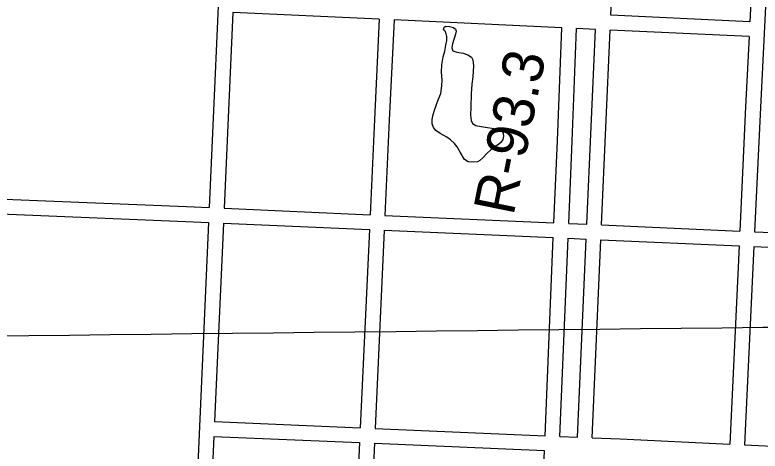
# Model space of a CAD drawing. Extents: x 3677843 to 3715951, y 511991 to 537744.
# Drawn here: x 3689113 to 3690620, y 529372 to 530256 of the extents above; entities that cross this region are included whole.
import ezdxf

# ---------------------------------------------------------------- set-up
doc = ezdxf.new("R2010")
doc.units = 0
for name, color, linetype in [('V-GRID-MAJR', 7, 'Continuous'), ('V-RIVR-RANG-IDEN', 7, 'Continuous'), ('V-ROAD-CNTR', 7, 'Continuous'), ('V-SITE-VEGE', 7, 'Continuous')]:
    doc.layers.add(name, color=color, linetype=linetype)

msp = doc.modelspace()

# ---------------------------------------------------------------- linework, layer by layer
at = {"layer": 'V-GRID-MAJR'}
msp.add_spline([(3681966.5640000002, 529526.479), (3687244.413, 529585.207), (3692522.254, 529644.703), (3697800.0870000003, 529704.966), (3703077.91, 529765.996), (3708355.725, 529827.795), (3713633.5300000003, 529890.361), (3713633.531, 529890.361)], degree=3, dxfattribs=at)
at = {"layer": 'V-ROAD-CNTR'}
for points in [[(3689565.7018297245, 531217.418538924), (3689532.1058969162, 530454.819064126), (3689506.0529490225, 529865.49324278)], [(3690663.22163468, 530926.6801204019), (3690620.55672001, 530068.1398374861), (3690608.7777435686, 529816.6893403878)], [(3690318.3653243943, 530254.923463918), (3690321.2293186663, 530319.5653346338), (3690336.838287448, 530648.7146763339)], [(3690618.57172398, 530632.622708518), (3690599.147762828, 530241.7594902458)], [(3689553.5558540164, 530260.7504522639), (3689536.022889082, 529864.1672454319)], [(3689850.0402610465, 530246.848480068), (3689553.5558540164, 530260.749452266)], [(3690599.147762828, 530241.7594902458), (3690318.3653243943, 530254.9244639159)], [(3689850.0402610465, 530246.8494800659), (3689840.321280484, 530043.7048863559), (3689831.436298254, 529851.0922715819)], [(3689880.007201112, 530245.4444828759), (3689870.287220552, 530042.2968891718), (3689861.407238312, 529849.7662742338)], [(3690219.0215230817, 530229.548514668), (3689880.007201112, 530245.443482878)], [(3690203.17755477, 529834.6383044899), (3690210.0625410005, 530000.9159719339), (3690219.019523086, 530229.548514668)], [(3690233.1484948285, 529833.3123071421), (3690240.0384810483, 529999.70797435), (3690248.98746315, 530228.143517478)], [(3690287.071386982, 530226.3585210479), (3690248.988463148, 530228.143517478)], [(3690269.5854219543, 529831.6993103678), (3690287.070386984, 530226.35752105)], [(3690299.556362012, 529830.37331302), (3690317.03732705, 530224.95252386)], [(3690597.6587658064, 530211.7965501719), (3690317.0383270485, 530224.9535238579)], [(3690597.6587658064, 530211.7965501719), (3690590.590779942, 530069.585834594), (3690578.80680351, 529818.0153377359)], [(3688823.97531318, 529893.349187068), (3689460.03404106, 529867.5302387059), (3689506.051949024, 529865.49324278)], [(3688822.627315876, 529863.3792470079), (3689458.762043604, 529837.5562986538), (3689504.727951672, 529835.522302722)], [(3689536.022889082, 529864.1662454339), (3689831.436298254, 529851.0922715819)], [(3689861.406238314, 529849.765274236), (3690203.17755477, 529834.639304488)], [(3689504.727951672, 529835.522302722), (3689479.68900175, 529269.140435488), (3689472.0690169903, 529093.9067859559)], [(3689534.6988917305, 529834.1963053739), (3689516.92892727, 529432.243109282)], [(3689534.697891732, 529834.1963053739), (3689830.05330102, 529821.124331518)], [(3690233.14749483, 529833.3133071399), (3690269.5854219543, 529831.7003103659)], [(3689830.054301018, 529821.124331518), (3689811.5353380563, 529419.6271345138)], [(3689860.025241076, 529819.7973341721), (3689841.50827811, 529418.3431370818)], [(3689860.0242410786, 529819.7973341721), (3690201.935557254, 529804.6653644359)], [(3690299.555362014, 529830.3743130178), (3690578.805803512, 529818.0143377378)], [(3690185.330590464, 529403.6181665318), (3690201.936557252, 529804.6643644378)], [(3690215.3025305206, 529402.3341690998), (3690231.90749731, 529803.33836709)], [(3690231.9064973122, 529803.33836709), (3690268.256424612, 529801.7303703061)], [(3690608.7767435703, 529816.68834039), (3690712.6365358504, 529812.0913495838)], [(3690250.495460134, 529400.8271721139), (3690268.25742461, 529801.7293703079)], [(3690280.4684001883, 529399.543174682), (3690298.228364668, 529800.4033729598)], [(3690298.22736467, 529800.4033729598), (3690577.4028063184, 529788.047397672)], [(3690577.4028063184, 529788.04839767), (3690558.5968439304, 529386.5782006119)], [(3690607.373746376, 529786.722400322), (3690588.562783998, 529385.1522034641)], [(3690607.372746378, 529786.7214003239), (3690711.310538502, 529782.121409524)], [(3689516.927927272, 529432.243109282), (3689811.5353380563, 529419.626134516)], [(3689841.50827811, 529418.342137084), (3690185.329590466, 529403.6181665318)], [(3689515.60392992, 529402.272169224), (3689509.6609418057, 529267.8264381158), (3689502.041957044, 529092.6447884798)], [(3689515.6029299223, 529402.272169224), (3689810.15334082, 529389.6581944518)], [(3690215.3025305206, 529402.3341690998), (3690250.495460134, 529400.8271721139)], [(3690280.4674001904, 529399.54417468), (3690337.116286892, 529397.1181795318), (3690558.595843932, 529386.5782006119)], [(3689810.15334082, 529389.6581944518), (3689795.88336936, 529080.268813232)], [(3689840.1262808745, 529388.3751970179), (3689825.857309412, 529079.0068157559)], [(3689840.125280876, 529388.3741970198), (3690184.088592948, 529373.64422648)], [(3690588.562783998, 529385.1522034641), (3690855.2192506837, 529372.462228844)], [(3690171.286618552, 529064.4578448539), (3690184.089592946, 529373.643226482)]]:
    msp.add_lwpolyline(points, dxfattribs=at)
at = {"layer": 'V-SITE-VEGE'}
msp.add_lwpolyline([(3689981.061, 530224.711), (3689979.879, 530226.638), (3689980.643, 530227.809), (3689981.003, 530230.527), (3689984.86, 530232.892), (3689991.845, 530232.186), (3690000.4, 530229.943), (3690004.3140000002, 530226.49), (3690005.514, 530222.626), (3690004.412, 530216.408), (3689998.006, 530197.343), (3689996.535, 530189.186), (3689998.923, 530183.005), (3690007.097, 530179.982), (3690019.915, 530177.783), (3690029.252, 530174.772), (3690036.2830000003, 530169.802), (3690039.0500000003, 530164.399), (3690040.717, 530152.781), (3690038.998, 530130.2710000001), (3690037.208, 530115.13), (3690035.845, 530096.115), (3690034.954, 530068.573), (3690034.339, 530052.279), (3690035.605, 530041.822), (3690038.765, 530036.037), (3690045.403, 530031.449), (3690055.89, 530029.612), (3690090.4590000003, 530024.138), (3690097.477, 530020.328), (3690100.6210000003, 530016.093), (3690101.065, 530010.281), (3690099.971, 530003.289), (3690096.531, 529998.214), (3690090.764, 529993.504), (3690083.055, 529988.386), (3690076.514, 529983.28), (3690067.6750000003, 529975.049), (3690059.233, 529966.046), (3690053.47, 529960.562), (3690048.839, 529958.188), (3690039.9280000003, 529957.326), (3690029.453, 529957.998), (3690022.035, 529962.966), (3690013.742, 529978.011), (3690007.435, 529988.419), (3690001.938, 529995.343), (3689993.721, 530002.63), (3689986.299, 530007.985), (3689973.041, 530015.61), (3689964.449, 530021.729), (3689959.352, 530027.496), (3689956.947, 530035.23), (3689957.248, 530044.153), (3689959.088, 530054.251), (3689962.473, 530064.756), (3689969.27, 530083.438), (3689974.181, 530096.672), (3689976.745, 530111.821), (3689977.0160000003, 530123.845), (3689975.699, 530139.344), (3689976.326, 530154.4720000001), (3689978.879, 530170.787), (3689982.254, 530182.452), (3689984.853, 530194.111), (3689986.701, 530203.436), (3689986.617, 530211.968), (3689985.398, 530217.385), (3689983.022, 530222.403)], close=True, dxfattribs=at)

# ---------------------------------------------------------------- texts
at = {"layer": 'V-RIVR-RANG-IDEN'}
msp.add_text('R-93.3', height=82.99999800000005, rotation=78.5718074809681, dxfattribs=at).set_placement((3690121.2290000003, 529847.4))

doc.saveas('drawing.dxf')
